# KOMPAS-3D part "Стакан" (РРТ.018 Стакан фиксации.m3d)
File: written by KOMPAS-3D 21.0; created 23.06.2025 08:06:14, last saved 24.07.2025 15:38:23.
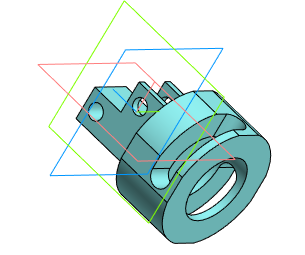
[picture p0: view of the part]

Document properties: Полное имя файла: C:\Users\User\Desktop\Ручной ротатор КД\Модели КД\РРТ.018 Стакан фиксации.m3d; Автор: User

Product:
- Part/product: Стакан
    Масса: 0.233412
    Форматы листов документа: A4
  - Body: Тело 1
      Масса: 0.233227

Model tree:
1. Эскиз:1
2. Элемент выдавливания:1
     Расстояние 1 = 13
3. Эскиз:2  (with: Элемент выдавливания:1)
4. Элемент выдавливания:2
     Расстояние 1 = 15
5. Эскиз:3
6. Элемент выдавливания:3
     Расстояние 1 = 30
7. Эскиз:5  (with: Элемент выдавливания:2)
8. Элемент выдавливания:4
     Расстояние 2 = 14
9. Эскиз:6
10. Элемент выдавливания:5
     Расстояние 2 = 24
11. Массив по концентрической сетке:1  (with: Элемент выдавливания:5, Эскиз:6, Элемент выдавливания:4)  (2 pattern instances)
     Шаг 2 = 360
12. Эскиз:7
13. Элемент выдавливания:6
     Расстояние 1 = 44
14. Эскиз:8  (with: Элемент выдавливания:1, Элемент выдавливания:3)
15. Элемент выдавливания:7
     Расстояние 2 = 24
16. Элемент выдавливания:11  (with: Элемент выдавливания:2)
     Расстояние 1 = 8
17. Эскиз:14  (with: Элемент выдавливания:1, Элемент выдавливания:7)
18. Элемент выдавливания:15
     Расстояние 2 = 12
